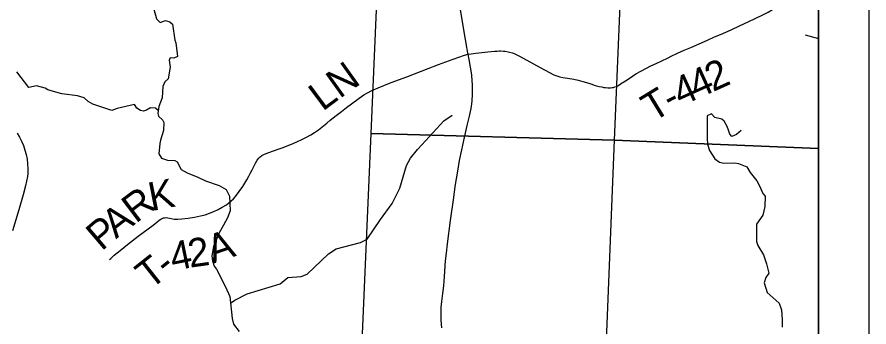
# Model space of a CAD drawing. Extents: x 0 to 34, y 0 to 22.
# Drawn here: x 7.308 to 9, y 15.804 to 16.42 of the extents above; entities that cross this region are included whole.
import ezdxf

# ---------------------------------------------------------------- set-up
doc = ezdxf.new("R2010")
doc.units = 0
for name, color, linetype in [('GM_X_County_Road', 7, 'Continuous'), ('GM_X_Minor_River', 7, 'Continuous'), ('GM_X_Rail_Line', 7, 'Continuous'), ('GM_X_Section', 7, 'Continuous'), ('GM_X_Township_Road', 7, 'Continuous'), ('GM_X_Township_Road_Text', 7, 'Continuous'), ('GM_X_Unincorporated_Text', 7, 'Continuous'), ('SH_Data', 7, 'Continuous')]:
    doc.layers.add(name, color=color, linetype=linetype)

msp = doc.modelspace()

# ---------------------------------------------------------------- linework, layer by layer
at = {"layer": 'GM_X_County_Road'}
for points in [[(8.2042, 16.3457), (8.2037, 16.3477), (8.2013, 16.3599), (8.196, 16.3904), (8.1856, 16.4548)], [(8.1516, 15.8023), (8.1505, 15.8177), (8.1503, 15.83), (8.1507, 15.8424), (8.1517, 15.8547), (8.1537, 15.8701), (8.1555, 15.8855), (8.157, 15.9041), (8.1593, 15.9351), (8.1607, 15.9505), (8.1628, 15.969), (8.1691, 16.0151), (8.1755, 16.0612), (8.1785, 16.0827), (8.1832, 16.1134), (8.187, 16.1347), (8.1913, 16.156), (8.1932, 16.1651), (8.1965, 16.1803), (8.2023, 16.2043), (8.2066, 16.2224), (8.2098, 16.2377), (8.2112, 16.2469), (8.212, 16.253), (8.2123, 16.2561), (8.2127, 16.2622), (8.2128, 16.2652), (8.2129, 16.2741), (8.2129, 16.2801), (8.2128, 16.2831), (8.2126, 16.2862), (8.2122, 16.2924), (8.211, 16.3048), (8.2088, 16.3202), (8.2063, 16.3355), (8.2042, 16.3457)], [(7.3081, 16.1892), (7.3129, 16.1812), (7.3172, 16.1728), (7.3208, 16.1642), (7.3239, 16.1553), (7.3263, 16.1463), (7.328, 16.1371), (7.3291, 16.1278), (7.3296, 16.1184), (7.3293, 16.109), (7.3287, 16.1028), (7.3272, 16.0936), (7.3252, 16.0844), (7.3201, 16.0665), (7.3114, 16.0367), (7.2988, 15.9951)]]:
    msp.add_lwpolyline(points, dxfattribs=at)
at = {"layer": 'GM_X_Minor_River'}
msp.add_line((8.8734, 16.3841), (8.9, 16.3772), dxfattribs=at)
for points in [[(7.5795, 16.4353), (7.5849, 16.4163), (7.5925, 16.4088), (7.6031, 16.4126), (7.6114, 16.41), (7.6167, 16.4051), (7.6214, 16.3736), (7.6234, 16.3683), (7.6269, 16.341), (7.6193, 16.3379), (7.6122, 16.3387), (7.6103, 16.3337), (7.6123, 16.3197), (7.6086, 16.2969), (7.6018, 16.2908), (7.5977, 16.2813), (7.5963, 16.2588), (7.5899, 16.2417), (7.5877, 16.2277), (7.5893, 16.2224)], [(7.5887, 16.2336), (7.5828, 16.2383), (7.5733, 16.2394), (7.5654, 16.2344), (7.559, 16.2328), (7.5533, 16.2336), (7.5461, 16.2385), (7.5415, 16.246), (7.5071, 16.2382), (7.4962, 16.234), (7.4587, 16.2467), (7.4492, 16.252), (7.4416, 16.2588), (7.4283, 16.2633), (7.3969, 16.2673), (7.3757, 16.2728), (7.3692, 16.2751), (7.3639, 16.2785), (7.3469, 16.2826), (7.3314, 16.2798), (7.3078, 16.3108)], [(8.7465, 16.1945), (8.7371, 16.1861), (8.728, 16.1822), (8.7238, 16.1871), (8.7211, 16.1947), (8.7184, 16.2023), (8.7126, 16.2125), (8.7077, 16.2166), (8.694, 16.2203), (8.6872, 16.2275), (8.6789, 16.2236), (8.6784, 16.1785), (8.6796, 16.1671), (8.6831, 16.1546), (8.6942, 16.138), (8.703, 16.1312), (8.7121, 16.129), (8.7333, 16.1299), (8.7412, 16.1288), (8.7572, 16.1217), (8.7641, 16.1107), (8.7774, 16.0945), (8.7832, 16.0828), (8.7894, 16.0692), (8.7936, 16.0639), (8.7933, 16.0434), (8.7893, 16.0259), (8.7765, 16.008), (8.7764, 15.9735), (8.7791, 15.9655), (8.7906, 15.9474), (8.7967, 15.9296), (8.801, 15.9106), (8.795, 15.9019), (8.7921, 15.8916), (8.7979, 15.8723), (8.8219, 15.8512), (8.8265, 15.8379), (8.8274, 15.8178), (8.8275, 15.8038)], [(7.5893, 16.2224), (7.5969, 16.2152), (7.5996, 16.2103), (7.5989, 16.1943), (7.5933, 16.1753), (7.5915, 16.1685), (7.59, 16.1476), (7.595, 16.1392), (7.6068, 16.1351), (7.6215, 16.1344), (7.6264, 16.1322), (7.6341, 16.1167), (7.6462, 16.1099), (7.6674, 16.1017), (7.6822, 16.0945)], [(7.7321, 15.8511), (7.7409, 15.8569), (7.7654, 15.8696), (7.8304, 15.8894), (7.8462, 15.902), (7.8727, 15.9041), (7.8844, 15.9091), (7.927, 15.9495), (7.9421, 15.9591), (7.9904, 15.972), (8.0037, 15.9785), (8.0299, 16.0177), (8.0532, 16.0494), (8.0685, 16.0798), (8.0818, 16.1247), (8.0893, 16.1391), (8.1032, 16.1567), (8.1122, 16.1658), (8.1555, 16.2132), (8.1724, 16.2246)], [(7.6822, 16.0945), (7.7098, 16.0852), (7.7235, 16.0773), (7.73, 16.064), (7.7313, 16.0348), (7.7261, 16.0204), (7.7183, 16.0063), (7.7097, 15.9911), (7.6985, 15.9637), (7.6952, 15.9451), (7.696, 15.9352), (7.6999, 15.9246), (7.7041, 15.9189), (7.7221, 15.8838), (7.7306, 15.8645), (7.7354, 15.8208), (7.7382, 15.8095), (7.7492, 15.7951)]]:
    msp.add_lwpolyline(points, dxfattribs=at)
at = {"layer": 'GM_X_Rail_Line'}
msp.add_lwpolyline([(6.4764, 15.22), (8.4272, 15.1429), (8.9, 15.1329), (8.9, 20.2439), (7.9141, 20.2806), (7.3096, 20.3035), (6.6357, 20.3306)], dxfattribs=at)
at = {"layer": 'GM_X_Section'}
for points in [[(8.0548, 17.2024), (8.5361, 17.186), (8.4938, 16.1751), (8.0113, 16.1881)], [(8.0113, 16.1881), (8.4938, 16.1751), (8.4531, 15.1468), (7.9673, 15.1628)]]:
    msp.add_lwpolyline(points, close=True, dxfattribs=at)
at = {"layer": 'GM_X_Township_Road'}
for points in [[(8.6196, 16.3476), (8.633, 16.3537), (8.646, 16.3592), (8.6793, 16.3739), (8.6933, 16.38), (8.7053, 16.3852), (8.7263, 16.3944), (8.7443, 16.4028), (8.7603, 16.4102), (8.7891, 16.424), (8.7999, 16.4292), (8.8087, 16.4343), (8.8165, 16.4391), (8.8246, 16.445), (8.8338, 16.4518), (8.8498, 16.4637), (8.864, 16.4742), (8.8729, 16.4813), (8.8814, 16.4868), (8.8879, 16.4908), (8.8929, 16.4933), (8.8977, 16.4956), (8.9, 16.4965)], [(7.4919, 15.938), (7.4941, 15.9402), (7.5008, 15.9465), (7.5127, 15.9559), (7.5277, 15.968), (7.5488, 15.9846), (7.5685, 15.9988), (7.5783, 16.0064), (7.5856, 16.0123), (7.5902, 16.0161), (7.5938, 16.0182), (7.5961, 16.0197), (7.5989, 16.0205), (7.6019, 16.0209), (7.6051, 16.0211), (7.6079, 16.0207), (7.6139, 16.0195), (7.6204, 16.0183), (7.6272, 16.0179), (7.6357, 16.0186), (7.648, 16.02), (7.6604, 16.0219), (7.6726, 16.0244), (7.6816, 16.0267), (7.6905, 16.0297), (7.6992, 16.0332), (7.7076, 16.0373), (7.7158, 16.0419), (7.7238, 16.0468), (7.7289, 16.0504), (7.7337, 16.0543), (7.7382, 16.0587), (7.7422, 16.0634), (7.7495, 16.0728), (7.7563, 16.0829), (7.7642, 16.0963), (7.7685, 16.1037), (7.7721, 16.1101), (7.7751, 16.1158), (7.7818, 16.1295), (7.7852, 16.1351), (7.7881, 16.1393), (7.7912, 16.1422), (7.7946, 16.1447), (7.7997, 16.147), (7.8085, 16.1507), (7.8172, 16.1537), (7.8269, 16.157), (7.8345, 16.1598), (7.853, 16.1668), (7.8637, 16.1716), (7.8748, 16.1768), (7.883, 16.1808), (7.8913, 16.1855), (7.8989, 16.1901), (7.9071, 16.1958), (7.9233, 16.2085), (7.9303, 16.2146), (7.9421, 16.2242), (7.9522, 16.2318), (7.9627, 16.2397), (7.9723, 16.2469), (7.9875, 16.2582), (7.997, 16.2647), (8.0041, 16.2687), (8.0127, 16.2734), (8.0252, 16.2792), (8.0365, 16.2837), (8.0512, 16.2894), (8.0823, 16.301), (8.1248, 16.3174), (8.1452, 16.3253), (8.1744, 16.3358), (8.197, 16.3436), (8.2042, 16.3457)], [(8.2042, 16.3457), (8.2099, 16.3465), (8.2191, 16.3479), (8.2432, 16.3503), (8.2561, 16.3515), (8.2618, 16.352), (8.2655, 16.3522), (8.2683, 16.3523), (8.2743, 16.3519), (8.2773, 16.3516), (8.2834, 16.3507), (8.2864, 16.35), (8.2923, 16.3482), (8.298, 16.3459), (8.3063, 16.3418), (8.3335, 16.3268), (8.3469, 16.3193), (8.3659, 16.3091), (8.3744, 16.305), (8.3802, 16.3028), (8.3862, 16.3009), (8.3923, 16.2996), (8.4015, 16.2982), (8.4137, 16.2959), (8.4227, 16.294), (8.4315, 16.2914), (8.4437, 16.2879), (8.4497, 16.2861), (8.4545, 16.2845), (8.459, 16.2831), (8.4644, 16.2818), (8.4693, 16.2807), (8.4733, 16.2798), (8.4767, 16.2793), (8.4811, 16.2788), (8.4868, 16.279), (8.4897, 16.2794), (8.4926, 16.2799), (8.4956, 16.2806), (8.4988, 16.2819), (8.5026, 16.2838), (8.5068, 16.2868), (8.5162, 16.2931), (8.5238, 16.2978), (8.5302, 16.302), (8.5372, 16.3065), (8.547, 16.3122), (8.5584, 16.3182), (8.567, 16.3225), (8.5777, 16.3275), (8.5889, 16.3325), (8.5997, 16.3379), (8.6083, 16.3422), (8.6168, 16.3463), (8.6196, 16.3476)]]:
    msp.add_lwpolyline(points, dxfattribs=at)
at = {"layer": 'GM_X_Unincorporated_Text'}
for points in [[(8.9, 16.1585), (8.9, 17.1728), (8.5361, 17.186), (8.4938, 16.1751)], [(8.9, 15.1321), (8.9, 16.1585), (8.4938, 16.1751), (8.4531, 15.1468), (8.4675, 15.1465)]]:
    msp.add_lwpolyline(points, close=True, dxfattribs=at)
at = {"layer": 'SH_Data'}
for p, q in [((9, 21), (9, 14)), ((8.9, 20.9), (8.9, 14.1))]:
    msp.add_line(p, q, dxfattribs=at)

# ---------------------------------------------------------------- texts
at = {"layer": 'GM_X_Township_Road_Text'}
for s, rotation, p in [('N', 35.5059, (7.9487, 16.2564)), ('2', 24.2209, (8.6901, 16.2704)), ('4', 24.2674, (8.6582, 16.256)), ('4', 24.4164, (8.6264, 16.2416)), ('L', 36.695, (7.9149, 16.2312)), ('T', 31.4084, (8.5709, 16.2097)), ('-', 26.9351, (8.6062, 16.2313)), ('K', 11.1628, (7.5751, 16.0339)), ('R', 37.0401, (7.5439, 16.0085)), ('A', 37.8644, (7.5046, 15.978)), ('P', 40.4225, (7.476, 15.9535)), ('A', 18.7284, (7.6971, 15.9292)), ('4', 11.6222, (7.618, 15.9146)), ('2', 8.2559, (7.6514, 15.9215)), ('T', 38.3272, (7.5726, 15.8767)), ('-', 38.4239, (7.6061, 15.9031))]:
    msp.add_text(s, height=0.0568, rotation=rotation, dxfattribs=at).set_placement(p)

doc.saveas('drawing.dxf')
